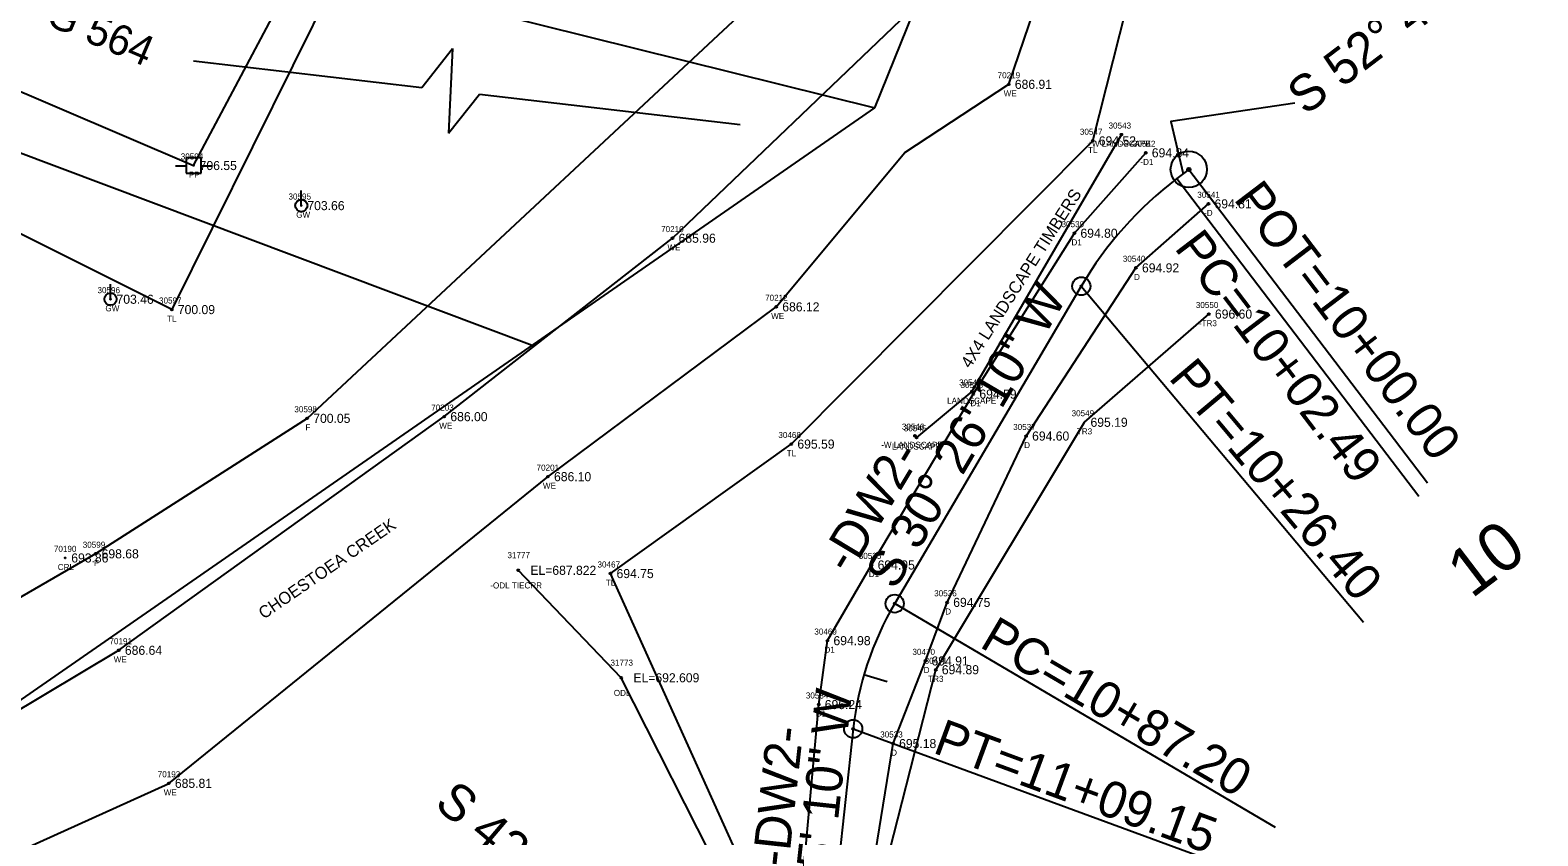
# Model space of a CAD drawing. Extents: x 1375131 to 1378678, y 999028 to 1004053.
# Drawn here: x 1377410.5 to 1377659.3, y 1001711.4 to 1001844.5 of the extents above; entities that cross this region are included whole.
import ezdxf

# ---------------------------------------------------------------- set-up
doc = ezdxf.new("R2010")
doc.units = 0
for name, color, linetype in [('RD_EX_BldgApp', 7, 'Continuous'), ('RD_EX_Driveway', 7, 'Continuous'), ('RD_EX_Driveway_txCode', 7, 'Continuous'), ('RD_EX_DV_Prop', 7, 'Continuous'), ('RD_EX_DV_TX_Prop(Owner ID)', 7, 'Continuous'), ('RD_EX_Fence_Other', 7, 'Continuous'), ('RD_EX_Fence_Other_txCode', 7, 'Continuous'), ('RD_EX_H2O', 7, 'Continuous'), ('RD_EX_H2O_txCode', 7, 'Continuous'), ('RD_EX_Misc_txCode', 7, 'Continuous'), ('RD_EX_SU_Elec', 7, 'Continuous'), ('RD_EX_TX_Driveway_ELEV', 7, 'Continuous'), ('RD_EX_TX_Fence_Other_ELEV', 7, 'Continuous'), ('RD_EX_TX_H2O_ELEV', 7, 'Continuous'), ('RD_EX_TX_UT_ELEV', 7, 'Continuous'), ('RD_EX_TX_VEG_ELEV', 7, 'Continuous'), ('RD_EX_UT', 7, 'Continuous'), ('RD_EX_UT_txCode', 7, 'Continuous'), ('RD_EX_VEG', 7, 'Continuous'), ('RD_EX_VEG_txCode', 7, 'Continuous'), ('RD_HC_Cl', 7, 'Continuous'), ('RD_HC_Data', 7, 'Continuous'), ('RD_HC_Data_Tic', 7, 'Continuous'), ('RD_HC_Survey_ELEV', 7, 'Continuous'), ('RD_HC_TX_Sta50', 7, 'Continuous'), ('RD_SMD_Locator', 7, 'Continuous'), ('RD_TX_Bldg', 7, 'Continuous'), ('RD_TX_Misc2', 7, 'Continuous')]:
    doc.layers.add(name, color=color, linetype=linetype)

msp = doc.modelspace()

# ---------------------------------------------------------------- linework, layer by layer
at = {"layer": 'RD_EX_BldgApp'}
msp.add_lwpolyline([(1377590.58, 1001827.2), (1377565.91, 1001784.77), (1377556.78, 1001777.2), (1377556.5, 1001777.48)], dxfattribs=at)
at = {"layer": 'RD_EX_Driveway'}
for points in [[(1377438.05, 1001602.19), (1377443.76, 1001603.95), (1377479.67, 1001621.19), (1377509.84, 1001640.05), (1377526.03, 1001657.08), (1377534.29, 1001677.17), (1377537.8, 1001701.74), (1377540.62, 1001733.09), (1377542.05, 1001743.64), (1377549.35, 1001756.14), (1377566.14, 1001784.36), (1377582.82, 1001810.92), (1377594.6, 1001824.2)], [(1377447.05, 1001595.81), (1377448.22, 1001596.07), (1377484.14, 1001614.6), (1377514.75, 1001633.36), (1377542.51, 1001658.65), (1377546.46, 1001672.71), (1377548.69, 1001700.51), (1377552.89, 1001726.65), (1377558.24, 1001740.29), (1377561.82, 1001749.96), (1377574.84, 1001777.43), (1377592.98, 1001805.2), (1377604.95, 1001815.77)]]:
    msp.add_lwpolyline(points, dxfattribs=at)
at = {"layer": 'RD_EX_DV_Prop'}
msp.add_line((1377380.13, 1001713.92), (1377549.86, 1001831.61), dxfattribs=at)
for points in [[(1377549.86, 1001831.61), (1377611.45, 1001984.12), (1377670.59, 1002066), (1377702.9, 1002207.93), (1377884.59, 1002382.26), (1377952.03, 1002369.22), (1378007.15, 1002415.65), (1377966.32, 1002503.97)], [(1377239.22, 1001933.68), (1377316.8, 1001925.5), (1377415.78, 1001865), (1377549.86, 1001831.61)], [(1377274.73, 1001874.68), (1377493.34, 1001792.42)]]:
    msp.add_lwpolyline(points, dxfattribs=at)
at = {"layer": 'RD_EX_DV_TX_Prop(Owner ID)'}
for p, q in [((1377437.41, 1001839.39), (1377475.09, 1001835)), ((1377475.09, 1001835), (1377480.2, 1001841.41)), ((1377480.2, 1001841.41), (1377479.52, 1001827.47)), ((1377479.52, 1001827.47), (1377484.63, 1001833.89)), ((1377484.63, 1001833.89), (1377527.67, 1001828.87))]:
    msp.add_line(p, q, dxfattribs=at)
at = {"layer": 'RD_EX_Fence_Other'}
msp.add_lwpolyline([(1377637.49, 1002082.79), (1377602.37, 1002057.58), (1377580.56, 1002027.27), (1377564.26, 1001923.93), (1377540.33, 1001858.9), (1377456.19, 1001780.35), (1377421.26, 1001757.98), (1377378.17, 1001733.06)], dxfattribs=at)
at = {"layer": 'RD_EX_H2O'}
for points in [[(1377375.48, 1001712.38), (1377425.1, 1001742.05), (1377478.82, 1001780.63), (1377516.49, 1001810.1), (1377555.39, 1001847.34), (1377570.71, 1001887.01), (1377585.15, 1001942.13), (1377603.16, 1001999.03), (1377641.82, 1002043.69), (1377653.81, 1002063.49)], [(1377385.63, 1001693.94), (1377390.69, 1001700.81), (1377433.35, 1001720.08), (1377495.93, 1001770.72), (1377533.61, 1001798.76), (1377554.83, 1001824.25), (1377571.99, 1001835.51), (1377587.87, 1001882.08), (1377602.65, 1001935.24), (1377621.67, 1001991.75), (1377650.41, 1002023.69), (1377680.27, 1002054.33)], [(1377531.81, 1001677.85), (1377524.79, 1001704.36), (1377508.04, 1001737.51), (1377491.03, 1001755.26)]]:
    msp.add_lwpolyline(points, dxfattribs=at)
at = {"layer": 'RD_EX_SU_Elec'}
msp.add_lwpolyline([(1377174.65, 1001934.87), (1377247.04, 1001903.65), (1377437.44, 1001822.1), (1377567.31, 1002066.68)], dxfattribs=at)
at = {"layer": 'RD_EX_UT'}
for p, q in [((1377434.47, 1001822.07), (1377436.21, 1001822.07)), ((1377438.69, 1001823.35), (1377436.19, 1001823.35)), ((1377436.19, 1001823.35), (1377436.19, 1001820.85)), ((1377438.65, 1001822.07), (1377440.47, 1001822.07)), ((1377438.69, 1001820.85), (1377438.69, 1001823.35)), ((1377436.19, 1001820.85), (1377438.69, 1001820.85)), ((1377455.22, 1001815.48), (1377455.22, 1001817.98)), ((1377423.72, 1001800.02), (1377423.72, 1001802.52))]:
    msp.add_line(p, q, dxfattribs=at)
for centre in [(1377455.22, 1001815.48), (1377423.72, 1001800.02)]:
    msp.add_circle(centre, 1, dxfattribs=at)
at = {"layer": 'RD_EX_VEG'}
for points in [[(1377636.58, 1002090.08), (1377595.82, 1002067.58), (1377573.9, 1002031.25), (1377561.3, 1002039.21), (1377460.46, 1001852.08), (1377433.84, 1001798.31), (1377321.3, 1001854.67)], [(1377442.63, 1001604.05), (1377477.59, 1001625.39), (1377503.97, 1001647.21), (1377512.81, 1001664.14), (1377526.59, 1001669.85), (1377529.57, 1001703.03), (1377506.25, 1001754.72), (1377536.1, 1001776.1), (1377585.85, 1001826.17), (1377602.61, 1001892.36), (1377617.88, 1001942.03), (1377660.76, 1002019.34), (1377674, 1002016.72), (1377712.55, 1001943.2)], [(1377577.84, 1001514.22), (1377523.1, 1001478.27), (1377519.66, 1001502.24), (1377466.46, 1001544.71), (1377441.17, 1001585.98), (1377464.76, 1001601.81), (1377468.99, 1001603.82), (1377550.07, 1001568.51), (1377532.63, 1001640.14), (1377553.09, 1001666.26), (1377550.19, 1001700.64), (1377559.94, 1001738.84), (1377584.48, 1001779.7), (1377605.02, 1001797.57)]]:
    msp.add_lwpolyline(points, dxfattribs=at)
at = {"layer": 'RD_HC_Cl'}
for p, q in [((1377601.71, 1001821.46), (1377599.73, 1001819.95)), ((1377583.96, 1001802.17), (1377553.16, 1001749.76)), ((1377546.31, 1001729.08), (1377540.51, 1001676.13))]:
    msp.add_line(p, q, dxfattribs=at)
for centre, radius, start, end in [((1377636.99, 1001771.02), 61.5, 127.2839, 149.5639), ((1377598, 1001723.41), 52, 149.5639, 173.7472)]:
    msp.add_arc(centre, radius, start, end, dxfattribs=at)
at = {"layer": 'RD_HC_Data'}
for p, q in [((1377599.73, 1001819.95), (1377639.67, 1001767.49)), ((1377601.71, 1001821.46), (1377641.1, 1001769.72)), ((1377583.96, 1001802.17), (1377630.53, 1001746.68)), ((1377553.16, 1001749.76), (1377615.97, 1001712.85)), ((1377546.31, 1001729.08), (1377609.49, 1001705.83))]:
    msp.add_line(p, q, dxfattribs=at)
msp.add_lwpolyline([(1377619.21, 1001832.38), (1377598.76, 1001829.35), (1377600.76, 1001820.74)], dxfattribs=at)
for centre, radius in [((1377601.71, 1001821.46), 3), ((1377601.71, 1001821.46), 0.282), ((1377583.96, 1001802.17), 1.5), ((1377583.96, 1001802.17), 0.141), ((1377553.16, 1001749.76), 1.5), ((1377553.16, 1001749.76), 0.141), ((1377546.31, 1001729.08), 1.5), ((1377546.31, 1001729.08), 0.141)]:
    msp.add_circle(centre, radius, dxfattribs=at)
at = {"layer": 'RD_HC_Data_Tic'}
for p, q in [((1377601.71, 1001821.46), (1377606.56, 1001815.09)), ((1377548.09, 1001738.03), (1377551.93, 1001736.91))]:
    msp.add_line(p, q, dxfattribs=at)
at = {"layer": 'RD_SMD_Locator'}
for centre, radius in [((1377571.99, 1001835.51), 0.15), ((1377590.58, 1001827.2), 0.15), ((1377585.85, 1001826.17), 0.15), ((1377594.6, 1001824.2), 0.15), ((1377437.44, 1001822.1), 0.075), ((1377601.71, 1001821.46), 0.15), ((1377455.22, 1001815.48), 0.075), ((1377604.95, 1001815.77), 0.15), ((1377516.49, 1001810.1), 0.15), ((1377582.82, 1001810.92), 0.15), ((1377592.98, 1001805.2), 0.15), ((1377423.72, 1001800.02), 0.075), ((1377433.84, 1001798.31), 0.15), ((1377533.61, 1001798.76), 0.15), ((1377605.02, 1001797.57), 0.15), ((1377565.91, 1001784.77), 0.15), ((1377566.14, 1001784.36), 0.15), ((1377456.19, 1001780.35), 0.15), ((1377478.82, 1001780.63), 0.15), ((1377556.5, 1001777.48), 0.15), ((1377556.78, 1001777.2), 0.15), ((1377574.84, 1001777.43), 0.15), ((1377536.1, 1001776.1), 0.15), ((1377495.93, 1001770.72), 0.15), ((1377416.25, 1001757.3), 0.075), ((1377421.26, 1001757.98), 0.15), ((1377491.03, 1001755.26), 0.15), ((1377506.25, 1001754.72), 0.15), ((1377549.35, 1001756.14), 0.15), ((1377561.82, 1001749.96), 0.15), ((1377425.1, 1001742.05), 0.15), ((1377542.05, 1001743.64), 0.15), ((1377558.24, 1001740.29), 0.15), ((1377508.04, 1001737.51), 0.15), ((1377559.94, 1001738.84), 0.15), ((1377540.62, 1001733.09), 0.15), ((1377552.89, 1001726.65), 0.15), ((1377433.35, 1001720.08), 0.15)]:
    msp.add_circle(centre, radius, dxfattribs=at)

# ---------------------------------------------------------------- texts
at = {"layer": 'RD_EX_Driveway_txCode'}
for s, p in [('30542', (1377592.48, 1001825.2)), ('-D1', (1377593.72, 1001822.2)), ('30541', (1377603.11, 1001816.77)), ('-D', (1377604.23, 1001813.77)), ('30539', (1377580.7, 1001811.92)), ('D1', (1377582.34, 1001808.92)), ('30540', (1377590.82, 1001806.2)), ('D', (1377592.67, 1001803.2)), ('30538', (1377564.02, 1001785.36)), ('D1', (1377565.67, 1001782.36)), ('30537', (1377572.72, 1001778.43)), ('D', (1377574.53, 1001775.43)), ('30535', (1377547.23, 1001757.14)), ('D1', (1377548.88, 1001754.14)), ('30536', (1377559.68, 1001750.96)), ('D', (1377561.51, 1001747.96)), ('30469', (1377539.9, 1001744.64)), ('D1', (1377541.57, 1001741.64)), ('30470', (1377556.09, 1001741.29)), ('D', (1377557.94, 1001738.29)), ('30534', (1377538.5, 1001734.09)), ('D1', (1377540.14, 1001731.09)), ('30533', (1377550.77, 1001727.65)), ('D', (1377552.58, 1001724.65))]:
    msp.add_text(s, height=1, dxfattribs=at).set_placement(p)
at = {"layer": 'RD_EX_DV_TX_Prop(Owner ID)'}
msp.add_text('INVOLVING PB A99 PG 5, PB P44 PG 564 ', height=5, rotation=336.9202, dxfattribs=at).set_placement((1377310.85, 1001888.92))
at = {"layer": 'RD_EX_Fence_Other_txCode'}
for s, p in [('30598', (1377454.07, 1001781.35)), ('F', (1377455.9, 1001778.35)), ('30599', (1377419.14, 1001758.98)), ('F', (1377420.98, 1001755.98))]:
    msp.add_text(s, height=1, dxfattribs=at).set_placement(p)
at = {"layer": 'RD_EX_H2O_txCode'}
for s, p in [('70219', (1377570.15, 1001836.51)), ('WE', (1377571.15, 1001833.51)), ('70210', (1377514.61, 1001811.1)), ('WE', (1377515.65, 1001808.1)), ('70212', (1377531.77, 1001799.76)), ('WE', (1377532.77, 1001796.76)), ('70203', (1377476.66, 1001781.63)), ('WE', (1377477.98, 1001778.63)), ('70201', (1377494.05, 1001771.72)), ('WE', (1377495.09, 1001768.72)), ('70190', (1377414.38, 1001758.3)), ('31777', (1377489.24, 1001757.26)), ('CRL', (1377415.02, 1001755.3)), ('-ODL TIECRR', (1377486.41, 1001752.26)), ('70191', (1377423.55, 1001743.05)), ('WE', (1377424.26, 1001740.05)), ('31773', (1377506.25, 1001739.51)), ('ODL', (1377506.8, 1001734.51)), ('70193', (1377431.52, 1001721.08)), ('WE', (1377432.51, 1001718.08))]:
    msp.add_text(s, height=1, dxfattribs=at).set_placement(p)
at = {"layer": 'RD_EX_Misc_txCode'}
for s, p in [('30543', (1377588.46, 1001828.2)), ('+W LANDSCAPE', (1377584.93, 1001825.2)), ('30544', (1377563.79, 1001785.77)), ('LANDSCAPE', (1377561.82, 1001782.77)), ('30546', (1377554.35, 1001778.48)), ('30545', (1377554.66, 1001778.2)), ('-W LANDSCAPE', (1377550.93, 1001775.48)), ('LANDSCAPE', (1377552.69, 1001775.2))]:
    msp.add_text(s, height=1, dxfattribs=at).set_placement(p)
at = {"layer": 'RD_EX_TX_Driveway_ELEV'}
for s, p in [('694.84', (1377595.6, 1001823.45)), ('694.81', (1377605.95, 1001815.02)), ('694.80', (1377583.82, 1001810.17)), ('694.92', (1377593.98, 1001804.45)), ('694.59', (1377567.14, 1001783.61)), ('694.60', (1377575.84, 1001776.68)), ('694.95', (1377550.35, 1001755.39)), ('694.75', (1377562.82, 1001749.21)), ('694.98', (1377543.05, 1001742.89)), ('694.91', (1377559.24, 1001739.54)), ('695.24', (1377541.62, 1001732.34)), ('695.18', (1377553.89, 1001725.9))]:
    msp.add_text(s, height=1.5, dxfattribs=at).set_placement(p)
at = {"layer": 'RD_EX_TX_Fence_Other_ELEV'}
for s, p in [('700.05', (1377457.19, 1001779.6)), ('698.68', (1377422.26, 1001757.23))]:
    msp.add_text(s, height=1.5, dxfattribs=at).set_placement(p)
at = {"layer": 'RD_EX_TX_H2O_ELEV'}
for s, p in [('686.91', (1377572.99, 1001834.76)), ('685.96', (1377517.49, 1001809.35)), ('686.12', (1377534.61, 1001798.01)), ('686.00', (1377479.82, 1001779.88)), ('686.10', (1377496.93, 1001769.97)), ('693.86', (1377417.25, 1001756.55)), ('EL=687.822', (1377493.03, 1001754.51)), ('686.64', (1377426.1, 1001741.3)), ('EL=692.609', (1377510.04, 1001736.76)), ('685.81', (1377434.35, 1001719.33))]:
    msp.add_text(s, height=1.5, dxfattribs=at).set_placement(p)
at = {"layer": 'RD_EX_TX_UT_ELEV'}
for s, p in [('703.66', (1377456.22, 1001814.73)), ('703.46', (1377424.72, 1001799.27))]:
    msp.add_text(s, height=1.5, dxfattribs=at).set_placement(p)
at = {"layer": 'RD_EX_TX_VEG_ELEV'}
for s, p in [('694.52', (1377586.85, 1001825.42)), ('700.09', (1377434.84, 1001797.56)), ('696.60', (1377606.02, 1001796.82)), ('695.19', (1377585.48, 1001778.95)), ('695.59', (1377537.1, 1001775.35)), ('694.75', (1377507.25, 1001753.97)), ('694.89', (1377560.94, 1001738.09))]:
    msp.add_text(s, height=1.5, dxfattribs=at).set_placement(p)
at = {"layer": 'RD_EX_UT_txCode'}
for s, p in [('30594', (1377435.32, 1001823.1)), ('PP', (1377436.66, 1001820.1)), ('30595', (1377453.1, 1001816.48)), ('GW', (1377454.38, 1001813.48)), ('30596', (1377421.58, 1001801.02)), ('GW', (1377422.88, 1001798.02))]:
    msp.add_text(s, height=1, dxfattribs=at).set_placement(p)
at = {"layer": 'RD_EX_VEG_txCode'}
for s, p in [('30547', (1377583.73, 1001827.17)), ('TL', (1377585.08, 1001824.17)), ('30597', (1377431.73, 1001799.31)), ('30550', (1377602.87, 1001798.57)), ('TL', (1377433.07, 1001796.31)), ('-TR3', (1377603.37, 1001795.57)), ('30549', (1377582.36, 1001780.7)), ('30468', (1377533.96, 1001777.1)), ('TR3', (1377583.23, 1001777.7)), ('TL', (1377535.33, 1001774.1)), ('30467', (1377504.11, 1001755.72)), ('TL', (1377505.48, 1001752.72)), ('30471', (1377558.1, 1001739.84)), ('TR3', (1377558.69, 1001736.84))]:
    msp.add_text(s, height=1, dxfattribs=at).set_placement(p)
at = {"layer": 'RD_HC_Data'}
for s, rotation, p in [('S 52%%d 42\' 58" W', 37.2839, (1377620.97, 1001830.26)), ('POT=10+00.00', 307.2839, (1377608.98, 1001816.56)), ('PC=10+02.49', 307.2839, (1377599.19, 1001808.48)), ('S 30%%d 26\' 10" W', 59.5639, (1377553.22, 1001751.83)), ('PT=10+26.40', 310.0037, (1377598.22, 1001786.99)), ('-DW2-', 58.9675, (1377545.75, 1001754.41)), ('PC=10+87.20', 329.5639, (1377566.99, 1001742.7)), ('S 6%%d 15\' 10" W', 83.7472, (1377540.52, 1001683.86)), ('PT=11+09.15', 339.794, (1377559.27, 1001725.19)), ('-DW2-', 83.7472, (1377535.59, 1001706.16)), ('S 42%%d 53\' 16" W', 319.7604, (1377476.98, 1001716.36))]:
    msp.add_text(s, height=6, rotation=rotation, dxfattribs=at).set_placement(p)
at = {"layer": 'RD_HC_Survey_ELEV'}
msp.add_text('706.55', height=1.5, dxfattribs=at).set_placement((1377438.44, 1001821.35))
at = {"layer": 'RD_HC_TX_Sta50'}
msp.add_text('10', height=8, rotation=37.2839, dxfattribs=at).set_placement((1377648.39, 1001750.48))
at = {"layer": 'RD_TX_Bldg'}
msp.add_text('4X4 LANDSCAPE TIMBERS', height=2, rotation=57.4304, dxfattribs=at).set_placement((1377565.62, 1001788.48))
at = {"layer": 'RD_TX_Misc2'}
msp.add_text('CHOESTOEA CREEK', height=2, rotation=34.6233, dxfattribs=at).set_placement((1377449.03, 1001747.11))

doc.saveas('drawing.dxf')
